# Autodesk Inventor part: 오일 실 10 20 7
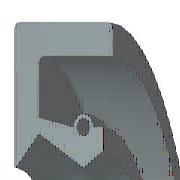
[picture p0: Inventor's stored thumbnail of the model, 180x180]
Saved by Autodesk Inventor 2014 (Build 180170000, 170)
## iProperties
IsCustomPart: 1
Created: 2012-02
Part Number: 오일 실 10 20 7
Material: 고무
Description: 오일-실
Document SubType Name: Modeling
Standard: KS B 2804
Designer: mduedu
Standards Organization: KS
Language: ko-KR
Size Designation: D - 10 20 7
Categories: <MemberInstance><Categories><Category DisplayName="샤프트 부품" InternalName="7f7aeb1f-a693-4053-b835-cee3144e0d98" Mnemonic="SHFT"><Category DisplayName="실링" Intern
Density: 0.93 g/cm^3
Appearance: 고무 - 검은색 - 버전 1.1
Author: mduedu
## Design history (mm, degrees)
revolve "본체" stored, may be unused: angle "d17" = 90 deg
revolve "스프링1" stored, may be unused: angle "d18" = 90 deg
body "Solid1"
sketch "스케치1"
  geometry: L1 (0, 10)-(7, 10); L2 (7, 8.25)-(1.75, 8.25); L3 (1.75, 6.75)-(4.9, 5); L4 (4.9, 5)-(0, 5); L5 (0, 0)-(9.586, 0) reference; L6 (4.9, 5)-(6.3, 5.875); L7 (0, 18)-(0, -3) reference; L8 (-1.941, 0)-(11.507, 0) reference; L9 (4.2, 7.1)-(1.75, 7.59); L10 (1.75, 7.59)-(1.75, 8.25); L11 (0, 10)-(0, 5.088); L12 (4.9, 5)-(0, 5); L13 (1.75, 6.75)-(0.152, 5.028); L14 (7, 10)-(7, 8.25); L15 (5.6, 7.1)-(6.3, 7.1); L16 (6.3, 7.1)-(6.3, 5.875); C1 r 0.455 at (4.9, 7.1); A1 r 0.7 centre (4.9, 7.1) between (5.6, 7.1) and (4.2, 7.1); A2 r 0.088 centre (0.088, 5.088) between (0, 5.088) and (0.152, 5.028); 1 further point
  constraints: 28 end point, 5 horizontal alignment, 5 point on line, 4 point on circle, 4 vertical alignment, 3 centre point, 3 tangent, 2 collinear, 2 horizontal, 2 perpendicular, 1 coincident, 1 parallel
  dimensions: "d0" = 20 diameter of L1 L5 (= SD2); "d1" = 1.75 distance of L1.end L2.start (= SD); "d2" = 0.91 diameter of C1 (= SPDI); "d3" = 1.4 diameter of A1 (= SPDA); "d4" = 10 diameter of L3.end L5 (= NND); "d5" = 13.5 diameter of L3.start L5 (= TKDM); "d7" = 15.18 diameter of L9.end L5 (= TKDM + 0.24 x SWDT); "d8" = 1.75 distance between parallel lines of L11 L10 (= SD); "d9" = 4.9 distance from line of L11 C1.centre (= SPDST); "d10" = 14.2 diameter of C1.centre L5 (= HLDM); "d11" = 0.0875 radius of A2 (= 0.25 x LAB); "d12" = 6.3 distance between parallel lines of L11 L16 (= SDI); "d13" = 11.75 diameter of L6.end L5 (= ABDM); "d14" = 7 distance from line of L11 L1.end (= SWDT)
fillet "모깎기1" dims "d6" = 0.3 (= RR)
other parameters: "SD2" = 20 [user parameter; used in 1 equation term], "SWDT" = 7 [user parameter; used in 2 equation terms], "RR" = 0.3 [user parameter; used in 1 equation term], "SD" = 1.75 [user parameter; used in 2 equation terms], "NND" = 10 [user parameter; used in 1 equation term], "SPDA" = 1.4 [user parameter; used in 1 equation term], "SPDI" = 0.91 [user parameter; used in 1 equation term], "TKDM" = 13.5 [user parameter; used in 2 equation terms], "HLDM" = 14.2 [user parameter; used in 1 equation term], "ABDM" = 11.75 [user parameter; used in 1 equation term], "SDI" = 6.3 [user parameter; used in 1 equation term], "SPDST" = 4.9 [user parameter; used in 1 equation term], "LAB" = 0.35 [user parameter; used in 1 equation term], "d15" = 0, "d16" = 0, "d19" = 0
